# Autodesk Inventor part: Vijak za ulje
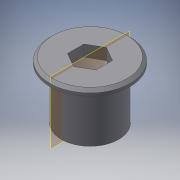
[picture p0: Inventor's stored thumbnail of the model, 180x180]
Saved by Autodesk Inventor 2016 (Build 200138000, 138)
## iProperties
Created: 2015-08
Part Number: Vijak za ulje
Material: Generic
Document SubType Name: Modeling
Designer: stank
Density: 1 g/cm^3
Appearance: Default
Mass: 6.33455 g
Surface Area: 26.9017 cm^2
Volume: 6.33455 cm^3
Author: stank
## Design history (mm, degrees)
sketch "Sketch1"
  geometry: C1 r 10 at (20, 15) reference; C2 r 10 at (20, 15); 1 further point
  constraints: 1 centre point, 1 coincident
  dimensions: "d1" = 20 diameter of C2
extrude "Extrusion1" new body sketch "Sketch1" distance "d2" = 18; taper "d3" = 0 deg
sketch "Sketch2"
  geometry: C1 r 14 at (0, 0); C2 r 10 at (0, 0) reference; 1 further point
  constraints: 1 centre point, 1 concentric
  dimensions: "d4" = 28 diameter of C1
extrude "Extrusion2" join sketch "Sketch2" distance "d5" = 2; taper "d6" = 0 deg
sketch "Sketch3"
  geometry: L1 (0, 5.774)-(5, 2.887); L2 (5, 2.887)-(5, -2.887); L3 (5, -2.887)-(0, -5.774); L4 (0, -5.774)-(-5, -2.887); L5 (-5, -2.887)-(-5, 2.887); L6 (-5, 2.887)-(0, 5.774); L7 (0, 0)-(0, 14.669); L8 (0, 0)-(16.025, 0); C1 r 14 at (0, 0) reference; 2 further points
  constraints: 16 end point, 1 coincident, 1 horizontal, 1 point on line, 1 vertical, 13 other
  dimensions: "d7" = 10 distance between parallel lines of L5 L2
extrude "Extrusion3" cut sketch "Sketch3" distance "d8" = 4; taper "d9" = 0 deg
workplane "Work Plane1"
sketch "Sketch4"
  geometry: L1 (0, 0)-(0, 5.774) reference; L2 (0, 2.887)-(9.767, 2.887); L3 (8.654, 2.887)-(4, 8.66); L4 (4, 8.66)-(4, 2.887); L5 (4, 0)-(4, 5.774) reference; L6 (4, 2.887)-(8.654, 2.887); 2 further points
  constraints: 8 end point, 2 midpoint, 1 coincident, 1 collinear, 1 horizontal, 1 point on line, 1 vertical
  dimensions: "d10" = 51.125 deg angle of L3 L2
revolve "Revolution1" sketch "Sketch4" stored, may be unused: angle "d11" = 90 deg
chamfer "Chamfer1" distance "d12" = 1; stored, may be unused: second distance "d13" = 2, angle "d14" = 45 deg
body "Solid1"
node "Reference2"
